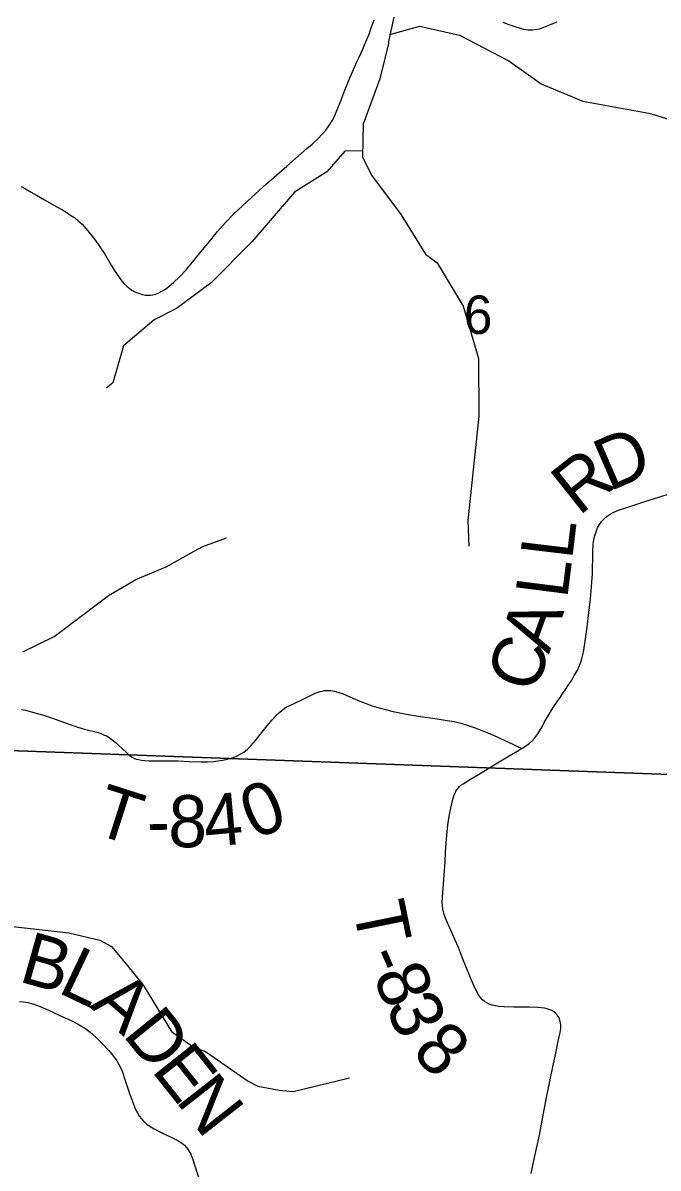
# Model space of a CAD drawing. Extents: x -2.1 to 31.9, y 6.3 to 28.3.
# Drawn here: x 4.635 to 5.327, y 24.409 to 25.658 of the extents above; entities that cross this region are included whole.
import ezdxf

# ---------------------------------------------------------------- set-up
doc = ezdxf.new("R2010")
doc.units = 0
for name, color, linetype in [('GM_X_County_Road', 7, 'Continuous'), ('GM_X_County_Road_Text', 7, 'Continuous'), ('GM_X_Minor_River', 7, 'Continuous'), ('GM_X_Section', 7, 'Continuous'), ('GM_X_Section_Text', 7, 'Continuous'), ('GM_X_Township_Road', 7, 'Continuous'), ('GM_X_Township_Road_Text', 7, 'Continuous')]:
    doc.layers.add(name, color=color, linetype=linetype)

msp = doc.modelspace()

# ---------------------------------------------------------------- linework, layer by layer
at = {"layer": 'GM_X_County_Road'}
msp.add_lwpolyline([(4.6308, 24.5903), (4.6351, 24.5901), (4.6377, 24.5898), (4.6399, 24.5893), (4.6453, 24.5879), (4.6536, 24.5848), (4.6626, 24.5809), (4.6747, 24.5753), (4.6888, 24.5688), (4.6958, 24.565), (4.7021, 24.5613), (4.708, 24.5568), (4.714, 24.5515), (4.7211, 24.5446), (4.7283, 24.537), (4.733, 24.5313), (4.7369, 24.5257), (4.7402, 24.5198), (4.7427, 24.5143), (4.7462, 24.5041), (4.7508, 24.4902), (4.7551, 24.4785), (4.7574, 24.4727), (4.7597, 24.4681), (4.7617, 24.4649), (4.7637, 24.4624), (4.7664, 24.4597), (4.7697, 24.4568), (4.7733, 24.4542), (4.7776, 24.4516), (4.7859, 24.4472), (4.7977, 24.4416), (4.8012, 24.4398), (4.8046, 24.438), (4.8068, 24.4366), (4.8087, 24.4352), (4.8105, 24.4336), (4.8125, 24.4315), (4.8141, 24.4296), (4.8158, 24.427), (4.8175, 24.4239), (4.8187, 24.4212), (4.8199, 24.4182), (4.8271, 24.3951)], dxfattribs=at)
at = {"layer": 'GM_X_Minor_River'}
for points in [[(5.0388, 25.6637), (5.0328, 25.6374), (5.0331, 25.6351), (5.0234, 25.5967), (5.0052, 25.5473), (5.0045, 25.5115), (5.0144, 25.4914), (5.0469, 25.4482), (5.0734, 25.4053), (5.0859, 25.3958), (5.1143, 25.3486)], [(5.0343, 25.6451), (5.0671, 25.6541), (5.1103, 25.6444), (5.1639, 25.6161), (5.1994, 25.591), (5.2446, 25.5721), (5.3164, 25.5592), (5.3625, 25.5452), (5.4235, 25.5383), (5.4373, 25.5333), (5.4505, 25.5306)], [(5.0047, 25.5181), (4.9852, 25.5178), (4.9656, 25.4953), (4.9305, 25.4731), (4.8841, 25.4189), (4.8396, 25.3743), (4.8019, 25.346), (4.7776, 25.3337), (4.7444, 25.3054), (4.7325, 25.2651), (4.7253, 25.2594)], [(5.1142, 25.3487), (5.1309, 25.2918), (5.1313, 25.2287), (5.1192, 25.1148), (5.1206, 25.0871)], [(4.6346, 24.9718), (4.6686, 24.9886), (4.6996, 25.0118), (4.7279, 25.0332), (4.7577, 25.0507), (4.7906, 25.0645), (4.8212, 25.0816), (4.8307, 25.0866), (4.8564, 25.0962)], [(4.3806, 24.7958), (4.389, 24.7709), (4.412, 24.7444), (4.4364, 24.7294), (4.4774, 24.7216), (4.5553, 24.7), (4.6139, 24.6733), (4.6846, 24.6653), (4.7184, 24.6572), (4.7313, 24.6504), (4.7443, 24.6349), (4.7661, 24.6077), (4.7964, 24.5577), (4.8201, 24.5411), (4.8337, 24.5359), (4.8799, 24.5034), (4.8905, 24.4982), (4.9137, 24.4937), (4.9289, 24.4923), (4.9903, 24.507)]]:
    msp.add_lwpolyline(points, dxfattribs=at)
at = {"layer": 'GM_X_Section'}
for points in [[(4.6345, 25.8828), (5.6902, 25.8357), (5.6296, 24.8273), (4.5692, 24.8661)], [(4.5692, 24.8661), (5.6296, 24.8273), (5.5612, 23.7889), (4.5062, 23.8498)]]:
    msp.add_lwpolyline(points, close=True, dxfattribs=at)
at = {"layer": 'GM_X_Township_Road'}
for points in [[(4.7645, 25.3615), (4.7654, 25.3613), (4.7683, 25.3607), (4.771, 25.3606), (4.7736, 25.3606), (4.776, 25.3609), (4.7791, 25.3617), (4.7826, 25.3631), (4.7859, 25.3649), (4.7892, 25.3669), (4.7936, 25.3701), (4.7992, 25.3749), (4.8054, 25.3806), (4.8129, 25.3886), (4.8284, 25.4078), (4.8379, 25.4194), (4.8467, 25.43), (4.8555, 25.44), (4.8644, 25.4493), (4.8737, 25.4582), (4.884, 25.4674), (4.9001, 25.482), (4.922, 25.5014), (4.9379, 25.5153), (4.9439, 25.5206), (4.9496, 25.5255), (4.9559, 25.5313), (4.9607, 25.5361), (4.9646, 25.5408), (4.9673, 25.5443), (4.9695, 25.5475), (4.9714, 25.5507), (4.9733, 25.5542), (4.9751, 25.5583), (4.9771, 25.5629), (4.9809, 25.5727), (4.9853, 25.5843), (4.99, 25.5958), (4.9937, 25.6044), (4.9985, 25.6151), (5.0008, 25.6202), (5.0052, 25.6298), (5.0069, 25.6338), (5.0094, 25.6395), (5.0117, 25.6455), (5.014, 25.6522), (5.0172, 25.661)], [(5.1576, 25.6583), (5.1641, 25.656), (5.1705, 25.6538), (5.1776, 25.6515), (5.18, 25.6508), (5.1824, 25.6504), (5.1848, 25.6501), (5.1872, 25.65), (5.1899, 25.65), (5.1927, 25.6503), (5.1952, 25.6507), (5.1988, 25.6516), (5.2023, 25.6528), (5.2165, 25.6588)], [(4.6327, 25.4792), (4.6373, 25.4768), (4.6437, 25.473), (4.6496, 25.4696), (4.6583, 25.4647), (4.6717, 25.457), (4.6776, 25.4536), (4.6876, 25.4473), (4.6911, 25.4449), (4.695, 25.4418), (4.6991, 25.438), (4.7037, 25.433), (4.7084, 25.4273), (4.7125, 25.4217), (4.7169, 25.4157), (4.7238, 25.4053), (4.7309, 25.3933), (4.7352, 25.3866), (4.7414, 25.3774), (4.7446, 25.3736), (4.7477, 25.3705), (4.7505, 25.3682), (4.7533, 25.3663), (4.7565, 25.3645), (4.7595, 25.3632), (4.7626, 25.362), (4.7645, 25.3615)], [(5.1883, 24.4027), (5.1921, 24.4203), (5.1974, 24.4446), (5.2005, 24.4605), (5.2056, 24.4877), (5.2119, 24.519), (5.2147, 24.5324), (5.2179, 24.547), (5.22, 24.5567), (5.2206, 24.561), (5.2207, 24.5641), (5.2204, 24.5672), (5.2197, 24.5702), (5.2187, 24.5725), (5.2175, 24.5747), (5.2163, 24.5763), (5.215, 24.5776), (5.2135, 24.5789), (5.2117, 24.5801), (5.2089, 24.5814), (5.2059, 24.5824), (5.2028, 24.583), (5.1994, 24.5835), (5.1955, 24.5838), (5.1861, 24.5842), (5.1768, 24.5843), (5.1694, 24.5844), (5.1588, 24.5847), (5.1533, 24.5851), (5.1495, 24.5857), (5.146, 24.5865), (5.1427, 24.5875), (5.1401, 24.5888), (5.1376, 24.5904), (5.1353, 24.5924), (5.1331, 24.5948), (5.1309, 24.5978), (5.1288, 24.6016), (5.1258, 24.6077), (5.1223, 24.6164), (5.1176, 24.628), (5.1137, 24.6378), (5.1091, 24.6492), (5.1057, 24.6573), (5.1021, 24.6658), (5.0987, 24.673), (5.0951, 24.6812), (5.0935, 24.6854), (5.0927, 24.6881), (5.092, 24.691), (5.0916, 24.6946), (5.0915, 24.6983), (5.0922, 24.7096), (5.0927, 24.7181), (5.0936, 24.7286), (5.0945, 24.7423), (5.0952, 24.7538), (5.0958, 24.763), (5.0965, 24.7718), (5.0977, 24.7829), (5.0991, 24.7921), (5.1009, 24.8012), (5.1031, 24.8109), (5.1046, 24.8157), (5.1054, 24.8177), (5.1064, 24.8198), (5.1074, 24.8215), (5.1087, 24.8232), (5.1102, 24.8248), (5.1119, 24.8262), (5.1144, 24.8279), (5.1223, 24.833), (5.1308, 24.838), (5.1482, 24.8486), (5.1645, 24.8585), (5.1757, 24.865), (5.1782, 24.8665), (5.182, 24.8689), (5.186, 24.8718), (5.1897, 24.8751), (5.1926, 24.8783), (5.1957, 24.8822), (5.1988, 24.8876), (5.2006, 24.8908), (5.2025, 24.8947), (5.2078, 24.9038), (5.2105, 24.908), (5.2132, 24.9122), (5.217, 24.9178), (5.2202, 24.9224), (5.223, 24.9265), (5.2258, 24.9306), (5.2292, 24.9358), (5.2326, 24.941), (5.2353, 24.9458), (5.2384, 24.9512), (5.2409, 24.9569), (5.2423, 24.9605), (5.2435, 24.9641), (5.2447, 24.9684), (5.2457, 24.9735), (5.2471, 24.9834), (5.2492, 24.9988), (5.2512, 25.0145), (5.2529, 25.0296), (5.2538, 25.0382), (5.2545, 25.0476), (5.255, 25.0567), (5.2552, 25.0629), (5.2554, 25.0735), (5.2556, 25.0815), (5.256, 25.0884), (5.2563, 25.092), (5.2569, 25.0953), (5.2578, 25.0987), (5.259, 25.1027), (5.2608, 25.1069), (5.2629, 25.1107), (5.2651, 25.1137), (5.268, 25.1169), (5.2713, 25.1197), (5.2744, 25.1219), (5.2785, 25.1242), (5.2835, 25.1262), (5.2924, 25.1293), (5.3156, 25.1366), (5.3262, 25.1399), (5.341, 25.1447)], [(4.6331, 24.9089), (4.6373, 24.9081), (4.645, 24.906), (4.6569, 24.9026), (4.6668, 24.8994), (4.6818, 24.8939), (4.6869, 24.892), (4.6943, 24.8896), (4.7017, 24.8875), (4.7167, 24.8836), (4.7198, 24.8826), (4.7226, 24.8813), (4.7256, 24.88), (4.7285, 24.8782), (4.7315, 24.8761), (4.7348, 24.8736), (4.7431, 24.866), (4.7474, 24.8619), (4.7501, 24.8593), (4.7529, 24.8573), (4.7553, 24.8558), (4.7579, 24.8548), (4.7605, 24.8542), (4.7637, 24.8536), (4.7676, 24.8532), (4.7718, 24.853), (4.7825, 24.8528), (4.7941, 24.8529), (4.8038, 24.8527), (4.8157, 24.8521), (4.8287, 24.8517), (4.8356, 24.8518), (4.8422, 24.8522), (4.8474, 24.8528), (4.8522, 24.8536), (4.8575, 24.8547), (4.8626, 24.8562), (4.8672, 24.858), (4.8713, 24.86), (4.8754, 24.8624), (4.8793, 24.8655), (4.8831, 24.8694), (4.888, 24.875), (4.8934, 24.8819), (4.8992, 24.8892), (4.9059, 24.8973), (4.9101, 24.9019), (4.9146, 24.9061), (4.9166, 24.9078), (4.9185, 24.9092), (4.9201, 24.9104), (4.9216, 24.9113), (4.9254, 24.9134), (4.9315, 24.9163), (4.9376, 24.9192), (4.9532, 24.9265), (4.9584, 24.9284), (4.9607, 24.929), (4.9632, 24.9294), (4.9663, 24.9295), (4.97, 24.9294), (4.9736, 24.9289), (4.9779, 24.9279), (4.9837, 24.9258), (4.9939, 24.9213), (5.0018, 24.9178), (5.0076, 24.9156), (5.0152, 24.9129), (5.0229, 24.9105), (5.0282, 24.9091), (5.0379, 24.9067), (5.0525, 24.9038), (5.0653, 24.9016), (5.086, 24.8985), (5.097, 24.8969), (5.1043, 24.8956), (5.1119, 24.8938), (5.1188, 24.8917), (5.1272, 24.8888), (5.1436, 24.8824), (5.1521, 24.8787), (5.1612, 24.8742), (5.1677, 24.8713), (5.1735, 24.8686), (5.1782, 24.8665)]]:
    msp.add_lwpolyline(points, dxfattribs=at)

# ---------------------------------------------------------------- texts
at = {"layer": 'GM_X_County_Road_Text'}
for s, rotation, p in [('B', 344.2757, (4.6288, 24.6126)), ('L', 334.585, (4.6713, 24.6009)), ('A', 319.2812, (4.7064, 24.5848)), ('D', 308.9574, (4.7424, 24.5541)), ('E', 308.4476, (4.7737, 24.5154)), ('N', 308.071, (4.8001, 24.4821))]:
    msp.add_text(s, height=0.0568, rotation=rotation, dxfattribs=at).set_placement(p)
at = {"layer": 'GM_X_Section_Text'}
msp.add_text('6', height=0.0419, rotation=0, dxfattribs=at).set_placement((5.1149, 25.3184))
at = {"layer": 'GM_X_Township_Road_Text'}
for s, rotation, p in [('D', 23.3981, (5.2733, 25.1462)), ('R', 38.4867, (5.2402, 25.1192)), ('L', 83.1536, (5.2329, 25.0713)), ('L', 82.7316, (5.2275, 25.0287)), ('A', 70.3854, (5.2076, 24.9686)), ('C', 70.9646, (5.1924, 24.9247)), ('T', 342.2776, (4.7094, 24.7743)), ('0', 22.7305, (4.8869, 24.7664)), ('8', 359.0556, (4.7927, 24.759)), ('4', 5.1397, (4.8339, 24.7587)), ('-', 1.3506, (4.7701, 24.7585)), ('T', 281.5419, (4.9937, 24.6937)), ('-', 293.6691, (5.0062, 24.6396)), ('8', 292.476, (5.0154, 24.6185)), ('3', 293.5432, (5.0292, 24.5851)), ('8', 315.7083, (5.0567, 24.5334))]:
    msp.add_text(s, height=0.0568, rotation=rotation, dxfattribs=at).set_placement(p)

doc.saveas('drawing.dxf')
